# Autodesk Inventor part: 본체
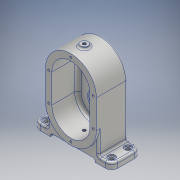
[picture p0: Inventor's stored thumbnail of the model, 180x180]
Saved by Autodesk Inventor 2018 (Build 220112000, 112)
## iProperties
Created: 2021-05
Part Number: 본체
Material: 알루미늄 6061
Document SubType Name: Modeling
Designer: admin
Density: 2.7 g/cm^3
Appearance: 알루미늄 - 평지
Author: admin
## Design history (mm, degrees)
sketch "스케치4"
  geometry: L1 (0, 0)-(0, 45); L2 (40, 0)-(40, 45); L3 (-40, 45)-(-40, 0); A1 r 40 centre (0, 0) between (-40, 0) and (40, 0); A2 r 40 centre (0, 45) between (40, 45) and (-40, 45); 1 further point
  constraints: 8 end point, 4 point on circle, 4 tangent, 2 centre point, 1 midpoint, 1 parallel, 1 vertical
  dimensions: "d13" = 45 distance of L1.start L1.end; "d14" = 80 distance between parallel lines of L3 L2
extrude "돌출4" new body sketch "스케치4" stored distance "d15" = 49; taper "d16" = 0 deg
sketch "스케치5"
  geometry: L1 (-40, 45)-(-40, 0) reference; L2 (40, 0)-(40, 45) reference; L3 (0, -65)-(0, 110) reference; L4 (-56, 0)-(56, 0) reference; L5 (0, 0)-(0, 45); L6 (30, 0)-(30, 45); L7 (-30, 45)-(-30, 0); A1 r 40 centre (0, 0) between (-40, 0) and (40, 0) reference; A2 r 40 centre (0, 45) between (40, 45) and (-40, 45) reference; A3 r 30 centre (0, 0) between (-30, 0) and (30, 0); A4 r 30 centre (0, 45) between (30, 45) and (-30, 45); 2 further points
  constraints: 8 end point, 4 point on circle, 4 tangent, 2 centre point, 1 collinear, 1 midpoint, 1 parallel
  dimensions: "d17" = 30 radius of A4
extrude "돌출5" cut sketch "스케치5" distance "d18" = 41; taper "d19" = 0 deg
sketch "스케치6"
  geometry: L1 (-40, 0)-(-40, -45) reference; L2 (40, -45)-(40, 0) reference; L3 (0, 0)-(0, -45); L4 (-26, 0)-(-26, -45); L5 (26, -45)-(26, 0); A1 r 40 centre (0, -45) between (-40, -45) and (40, -45) reference; A2 r 40 centre (0, 0) between (40, 0) and (-40, 0) reference; A3 r 26 centre (0, 0) between (26, 0) and (-26, 0); A4 r 26 centre (0, -45) between (-26, -45) and (26, -45); 2 further points
  constraints: 8 end point, 4 point on circle, 4 tangent, 2 centre point, 1 midpoint, 1 parallel, 1 vertical
  dimensions: "d20" = 52 distance between parallel lines of L4 L5
extrude "돌출6" join sketch "스케치6" distance "d21" = 11; taper "d22" = 0 deg
node "작업 평면1"
sketch "스케치7"
  geometry: L1 (-61, 24.5)-(61, 24.5); L2 (61, 24.5)-(61, -21.5); L3 (61, -21.5)-(-61, -21.5); L4 (-61, -21.5)-(-61, 24.5); L5 (-61, 24.5)-(61, -21.5); L6 (61, 24.5)-(-61, -21.5); L7 (0, -42.635)-(0, 84.311) reference; L8 (-85.4, 0)-(85.4, 0) reference; 4 further points
  constraints: 12 end point, 3 midpoint, 2 parallel, 2 point on line, 1 horizontal, 1 perpendicular
  dimensions: "d24" = 122 distance of L1.start L1.end; "d25" = 46 distance of L1.end L2.end
extrude "돌출7" join sketch "스케치7" distance "d26" = 10; taper "d27" = 0 deg
sketch "스케치8"
  geometry: L1 (-40, 0)-(-40, -45) reference; L2 (40, -45)-(40, 0) reference; L3 (61, 37)-(15.199, 37) reference; L4 (61, 47)-(61, 37) reference; L5 (-61, 47)-(61, 47) reference; L6 (-61, 47)-(-61, 37) reference; L7 (-15.199, 37)-(-61, 37) reference; L8 (26, 0)-(26, -45) reference; L9 (-26, -45)-(-26, 0) reference; L10 (0, 73.4)-(0, -111.4) reference; L11 (-85.4, 0)-(85.4, 0) reference; L12 (40, 0)-(40, 37); L13 (-40, 0)-(-40, 37); L14 (-15.199, 37)-(-61, 37) reference; L15 (40, 37)-(15.199, 37); L16 (-15.199, 37)-(-40, 37); A1 r 40 centre (0, 0) between (-15.199, 37) and (-40, 0) reference; A2 r 40 centre (0, -45) between (-40, -45) and (40, -45) reference; A3 r 40 centre (0, 0) between (40, 0) and (15.199, 37) reference; A4 r 26 centre (0, 0) between (26, 0) and (-26, 0) reference; A5 r 26 centre (0, -45) between (-26, -45) and (26, -45) reference; 1 further point
  constraints: 8 end point, 2 perpendicular, 2 point on line, 1 collinear
extrude "돌출8" join sketch "스케치8" stored distance "d28" = 10; taper "d29" = 0 deg
sketch "스케치9"
  geometry: L1 (61, -26.4)-(61, 158.4) reference; L2 (-24.4, 47)-(146.4, 47) reference; L3 (21, 10)-(21, 47) reference; L4 (0, 10)-(21, 10) reference; L5 (0, 0)-(0, 10) reference; L6 (122, 0)-(0, 0) reference; L7 (122, 0)-(122, 10) reference; L8 (101, 10)-(122, 10) reference; L9 (101, 47)-(101, 10) reference; L10 (26, 0)-(96, 0); L11 (96, 0)-(96, 5); L12 (96, 5)-(26, 5); L13 (26, 5)-(26, 0); L14 (26, 0)-(96, 5); L15 (96, 0)-(26, 5); L16 (122, 0)-(0, 0) reference; A1 r 40 centre (61, 47) between (21, 47) and (101, 47) reference; 2 further points
  constraints: 12 end point, 2 midpoint, 2 parallel, 2 point on line, 1 horizontal, 1 perpendicular
  dimensions: "d30" = 70 distance of L12.end L11.end; "d31" = 5 distance of L11.end L10.end
extrude "돌출9" cut sketch "스케치9" stored distance "d32" = 10; taper "d33" = 0 deg
fillet "모깎기1" dims "d34" = 10
sketch "스케치10"
  geometry: L1 (-51, 24.5)-(-35, 24.5) reference; L2 (-35, 24.5)-(-35, -21.5) reference; L3 (-35, -21.5)-(-51, -21.5) reference; L4 (-61, -11.5)-(-61, 14.5) reference; L5 (61, 14.5)-(61, -11.5) reference; L6 (51, -21.5)-(35, -21.5) reference; L7 (35, -21.5)-(35, 24.5) reference; L8 (35, 24.5)-(51, 24.5) reference; L9 (-88.299, 0)-(88.299, 0) reference; L10 (0, -36.5)-(0, 47.5) reference; A1 r 10 centre (-51, 14.5) between (-51, 24.5) and (-61, 14.5) reference; A2 r 10 centre (-51, -11.5) between (-61, -11.5) and (-51, -21.5) reference; A3 r 10 centre (51, 14.5) between (61, 14.5) and (51, 24.5) reference; A4 r 10 centre (51, -11.5) between (51, -21.5) and (61, -11.5) reference; 5 further points
  constraints: 4 coincident
hole "구멍1" sketch "스케치10" at (-51, -11.5), (-51, 14.5), (51, 14.5), (51, -11.5) diameter "d35" = 6.6; stored, may be unused: countersink angle "d39" = 90 deg, drill point angle "d41" = 118 deg; dims "d36" = 6, "d37" = 11, "d38" = 2, "d40" = 8
sketch "스케치11"
  geometry: L1 (-26, 0)-(-26, -45) reference; L2 (26, -45)-(26, 0) reference; L3 (-85.4, 0)-(85.4, 0) reference; L4 (0, 73.4)-(0, -111.4) reference; L5 (26, -15)-(-26, -15); L6 (26, -15)-(26, -45); L7 (-26, -45)-(-26, 0) reference; L8 (-26, -15)-(-26, -45); A1 r 26 centre (0, -45) between (-26, -45) and (26, -45) reference; A2 r 26 centre (0, 0) between (26, 0) and (-26, 0) reference; A3 r 26 centre (0, -45) between (-26, -45) and (26, -45) reference; 2 further points
  constraints: 6 end point, 2 point on line, 1 coincident, 1 collinear, 1 horizontal, 1 horizontal alignment, 3 other
  dimensions: "d42" = 30 distance from line of L5 A1.centre
extrude "돌출10" cut sketch "스케치11" distance "d43" = 3; taper "d44" = 0 deg
sketch "스케치12"
  geometry: L1 (16.5, 45)-(16.5, 0) reference; L2 (16.5, 45)-(16.5, 45) reference; L3 (16.5, 0)-(16.5, 45) reference; L4 (16.5, 0)-(16.5, 0) reference; L5 (0, -73.4)-(0, 111.4) reference; L6 (-36.5, 0)-(47.5, 0) reference; L7 (-43.665, 45)-(58.067, 45); L8 (16.5, 59)-(24.5, 59); L9 (24.5, 59)-(24.5, 56); L10 (24.5, 56)-(28.5, 56); L11 (28.5, 56)-(28.5, 59); L12 (28.5, 59)-(32.5, 59); L13 (32.5, 71)-(32.5, 45) reference; L14 (16.5, 45)-(16.5, 75) reference; L15 (24.5, 45)-(32.5, 45) reference; L16 (16.5, 45)-(32.5, 45); 1 further point
  constraints: 14 end point, 4 perpendicular, 3 horizontal, 3 point on line
  dimensions: "d47" = 8 distance of L8.start L8.end; "d48" = 4 distance of L11.end L12.end; "d49" = 28 diameter of L8 L7; "d50" = 28 diameter of L12 L7; "d51" = 22 diameter of L10 L7
revolve "회전1" sketch "스케치12" stored, may be unused: angle "d52" = 90 deg
sketch "스케치13"
  geometry: L1 (30, 45)-(30, 0) reference; L2 (-30, 0)-(-30, 45) reference; C1 r 14 at (0, 45) reference; C2 r 14 at (0, 0); A1 r 30 centre (0, 45) between (30, 45) and (-30, 45) reference; A2 r 30 centre (0, 0) between (-30, 0) and (30, 0) reference; 1 further point
  constraints: 1 centre point, 1 coincident
  dimensions: "d53" = 28 diameter of C2
extrude "돌출11" cut sketch "스케치13" distance "d54" = 8; taper "d55" = 0 deg
sketch "스케치14"
  geometry: C1 r 10 at (0, 0); 1 further point
  constraints: 1 centre point, 1 coincident
  dimensions: "d56" = 20 diameter of C1
extrude "돌출12" cut sketch "스케치14" distance "d57" = 4; taper "d58" = 0 deg
sketch "스케치15"
  geometry: L1 (30, 45)-(30, 0) reference; L2 (-30, 0)-(-30, 45) reference; L3 (-40, 45)-(-40, 0) reference; L4 (40, 0)-(40, 45) reference; L5 (0, -73.4)-(0, 111.4) reference; L6 (-85.4, 0)-(85.4, 0) reference; L7 (0, 45)-(0, 0); L8 (-35, 45)-(-35, 0); L9 (35, 0)-(35, 45); L10 (-82.081, 22.5)-(84.009, 22.5); A1 r 30 centre (0, 45) between (30, 45) and (-30, 45) reference; A2 r 30 centre (0, 0) between (-30, 0) and (30, 0) reference; A3 r 40 centre (0, 0) between (-40, 0) and (40, 0) reference; A4 r 40 centre (0, 45) between (40, 45) and (-40, 45) reference; A5 r 35 centre (0, 45) between (35, 45) and (-35, 45); A6 r 35 centre (0, 0) between (-35, 0) and (35, 0); 8 further points
  constraints: 10 end point, 5 point on circle, 4 tangent, 3 symmetric about line, 2 centre point, 2 coincident, 1 collinear, 1 horizontal, 1 midpoint, 1 parallel, 1 point on line
  dimensions: "d59" = 35 radius of A5
hole "구멍2" sketch "스케치15" at (-35, 0), (0, -35), (35, 0), (-35, 45), (0, 80), (35, 45) diameter "d60" = 3.242; stored, may be unused: countersink angle "d64" = 90 deg, drill point angle "d66" = 118 deg; dims "d61" = 8, "d62" = 11, "d63" = 2, "d65" = 10
sketch "스케치16" dims "d67" = 40
  geometry: L1 (0, 73.4)-(0, -111.4) reference; L2 (-85.4, 0)-(85.4, 0) reference; C1 r 11 at (0, -45) reference; 5 further points
  constraints: 1 coincident, 1 point on line, 1 vertical alignment, 6 other
  dimensions: "d70" = 360 deg dimension on point (0, -45) point (0, -65) (derived)
hole "구멍3" sketch "스케치16" at (0, -65), (17.321, -35), (-17.321, -35) diameter "d72" = 3.242; stored, may be unused: countersink angle "d76" = 90 deg, drill point angle "d78" = 118 deg; dims "d73" = 8, "d74" = 11, "d75" = 2, "d77" = 10
node "작업 평면2"
sketch "스케치17"
  geometry: L1 (0, -36.5)-(0, 47.5) reference; L2 (-85.4, 0)-(85.4, 0) reference; L3 (-40, -24.5)-(40, -24.5) reference; C1 r 6 at (0, -3.5); 1 further point
  constraints: 1 centre point, 1 point on line
  dimensions: "d80" = 12 diameter of C1; "d81" = 21 distance from line of L3 C1.centre
extrude "돌출13" join sketch "스케치17" stored distance "d82" = 4; taper "d83" = 0 deg
sketch "스케치18"
  geometry: C1 r 6 at (0, 0) reference; 2 further points
  constraints: 1 coincident
hole "구멍4" sketch "스케치18" at (0, 0) diameter "d84" = 4.917; stored, may be unused: countersink angle "d88" = 90 deg, drill point angle "d90" = 118 deg; dims "d85" = 30, "d86" = 11, "d87" = 2, "d89" = 30
fillet "모깎기2" dims "d91" = 3
sketch "스케치19"
  geometry: L1 (35, -15)-(35, 69) reference; L2 (120.4, 21.5)-(-50.4, 21.5) reference; L3 (-5, -3)-(75, -3) reference; 2 further points
  constraints: 1 point on line
  dimensions: "d92" = 21 distance from line of point (35, 18) L3
hole "구멍5" sketch "스케치19" at (35, 18) diameter "d93" = 4.917; stored, may be unused: countersink angle "d97" = 90 deg, drill point angle "d99" = 118 deg; dims "d94" = 30, "d95" = 11, "d96" = 2, "d98" = 30
sketch "스케치20"
  geometry: C1 r 2.458 at (35, 18) reference; C2 r 6 at (35, 18); 1 further point
  constraints: 1 centre point, 1 coincident
  dimensions: "d100" = 12 diameter of C2
extrude "돌출14" cut sketch "스케치20" distance "d101" = 1; taper "d102" = 0 deg
fillet "모깎기3" dims "d103" = 5
fillet "모깎기4" dims "d104" = 0.3
chamfer "모따기1" distance "d105" = 1; stored, may be unused: second distance "d106" = 2, angle "d107" = 45 deg
fillet "모깎기5" dims "d108" = 3
sketch "스케치21"
  geometry: L1 (0, 74.006)-(0, -115.034) reference; L2 (-85.4, 0)-(85.4, 0) reference; L3 (35, 47)-(51, 47) reference; 2 further points
  constraints: 1 point on line, 1 other
  dimensions: "d109" = 12 distance from line of L3 point (0, 35)
feature "엠보싱1" sketch "스케치21" dims "d110" = 0.5, "d111" = 0
fillet "모깎기6" dims "d112" = 3
node "솔리드2"
node "투영된 루프2"
node "투영된 루프3"
node "투영된 루프4"
node "투영된 루프5"
node "투영된 루프6"
node "투영된 루프7"
node "투영된 루프8"
node "투영된 루프9"
node "투영된 루프10"
node "투영된 루프11"
node "투영된 루프12"
other parameters: "d23" = -47, "d79" = 88
